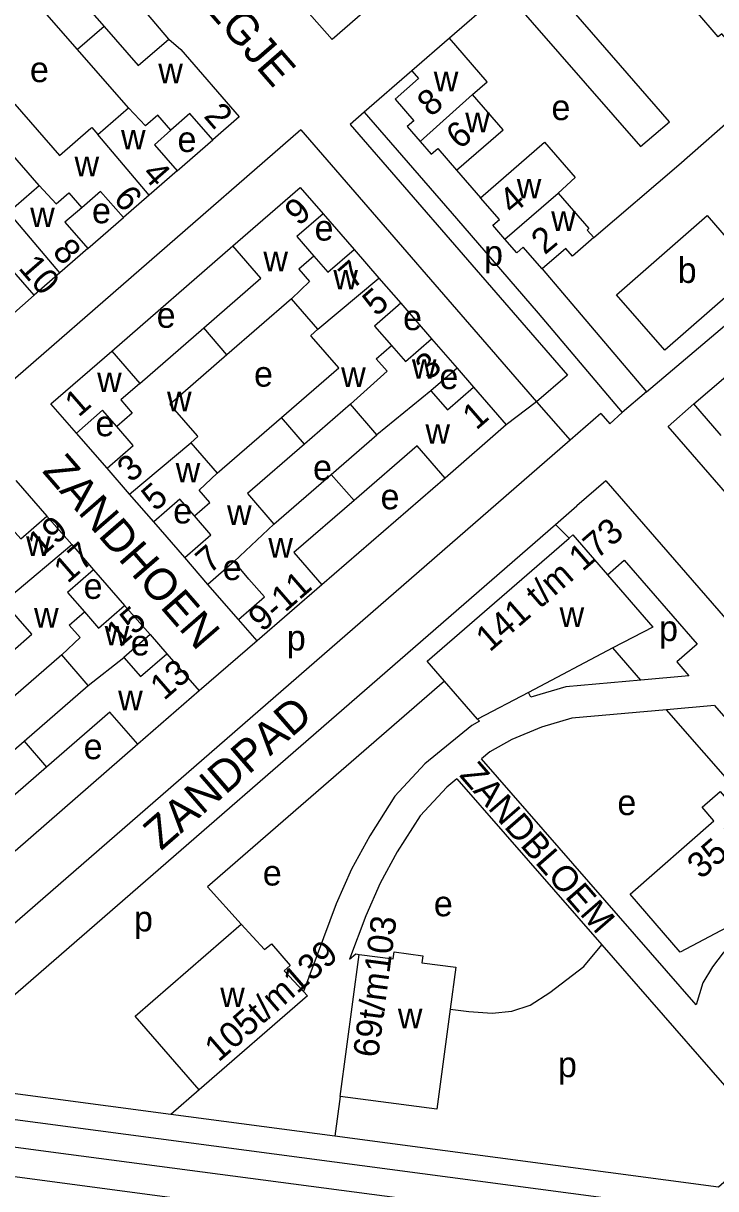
# Model space of a CAD drawing. Extents: x 155854 to 157362, y 383621 to 384685.
# Drawn here: x 156185.4 to 156294.2, y 383977 to 384160.1 of the extents above; entities that cross this region are included whole.
import ezdxf

# ---------------------------------------------------------------- set-up
doc = ezdxf.new("R2010")
doc.units = 0
for name, color, linetype in [('BLT_Basislijn', 7, 'Continuous'), ('BLT_Bebouwing', 7, 'Continuous'), ('BLT_Centroide', 7, 'Continuous'), ('BLT_Huisnummer', 7, 'Continuous'), ('BLT_Huisnummer_ tussenligend', 7, 'Continuous'), ('BLT_Huisnummer_reeks', 7, 'Continuous'), ('BLT_Onderverdeling_panden', 7, 'Continuous'), ('BLT_Straatnaam', 7, 'Continuous'), ('BLT_Straatnaam_verkleind', 7, 'Continuous')]:
    doc.layers.add(name, color=color, linetype=linetype)

msp = doc.modelspace()

# ---------------------------------------------------------------- linework, layer by layer
at = {"layer": 'BLT_Basislijn'}
for p, q in [((156208.25, 384157.66), (156195.11, 384173.27)), ((156261.02, 384165.3), (156252.38, 384157.81)), ((156246.43, 384152.66), (156238.97, 384146.18)), ((156288.38, 384137.89), (156302.08, 384149.93)), ((156238.97, 384146.18), (156236.73, 384144.23)), ((156238.97, 384146.18), (156253.47, 384129.45)), ((156228.99, 384143.37), (156119.21, 384047.9)), ((156209.57, 384136.94), (156215.16, 384141.83)), ((156253.48, 384137.07), (156257.24, 384132.72)), ((156275.02, 384126.47), (156288.38, 384137.89)), ((156195.52, 384124.75), (156201.13, 384129.6)), ((156232.5, 384130.2), (156237.37, 384124.59)), ((156199.29, 384108.63), (156218.31, 384125.15)), ((156283.29, 384102.22), (156307.03, 384122.29)), ((156181.54, 384112.55), (156187.1, 384117.41)), ((156244.7, 384116.14), (156249.55, 384110.55)), ((156253.55, 384105.95), (156256.15, 384102.97)), ((156270.89, 384104.85), (156266.05, 384100.66)), ((156283.29, 384102.22), (156279.5, 384098.96)), ((156266.05, 384100.66), (156261.29, 384097.05)), ((156266.05, 384100.66), (156271.3, 384094.61)), ((156286.74, 384096.77), (156290.76, 384100.33)), ((156276.14, 384098.81), (156271.3, 384094.61)), ((156276.14, 384098.81), (156277.53, 384097.2)), ((156279.5, 384098.96), (156277.53, 384097.2)), ((156198.56, 384090.23), (156193.75, 384095.75)), ((156184.24, 384088.28), (156189.1, 384082.69)), ((156251.66, 384088.68), (156232.31, 384071.9)), ((156276.92, 384088.24), (156272.39, 384084.3)), ((156210.77, 384076.18), (156205.89, 384081.79)), ((156269.03, 384081.38), (156271.15, 384079.26)), ((156196.45, 384074.27), (156201.32, 384068.67)), ((156219.2, 384066.47), (156214.4, 384071.98)), ((156205.31, 384064.1), (156207.93, 384061.07)), ((156222.13, 384063.09), (156213.04, 384055.23)), ((156282.43, 384056.94), (156278.04, 384061.99)), ((156289.95, 384057.62), (156282.43, 384056.94)), ((156293.99, 384052.96), (156286.48, 384052.28)), ((156293.99, 384052.96), (156302.93, 384042.66)), ((156298.33, 384038.66), (156286.48, 384052.28)), ((156203.42, 384046.86), (156184.1, 384030.05)), ((156291.12, 384005.94), (156257.4, 384044.59)), ((156253.52, 384041.43), (156276.3, 384015.32)), ((156213.04, 383992.55), (156208.6, 383988.69)), ((156235.2, 383991.54), (156234.37, 383985.27)), ((156189.73, 383982.81), (156254.44, 383974.29))]:
    msp.add_line(p, q, dxfattribs=at)
for points in [[(156274.95, 384193.23), (156233.91, 384157.58), (156227.55, 384164.87)], [(156284.47, 384142.57), (156286.91, 384144.67), (156265.55, 384169.24)], [(156261.02, 384165.3), (156282.35, 384140.75), (156284.47, 384142.57)], [(156236.73, 384144.23), (156270.89, 384104.85)], [(156228.99, 384143.37), (156266.05, 384100.66)], [(156253.47, 384129.45), (156266.29, 384114.57), (156279.5, 384098.96)], [(156266.94, 384121.54), (156270.1, 384117.8), (156283.29, 384102.22)], [(156324.05, 384062.01), (156320.05, 384058.42), (156286.74, 384096.77)], [(156271.3, 384094.61), (156165.88, 384003.01), (156161.13, 383998.95)], [(156276.92, 384088.24), (156307.18, 384053.41), (156310.96, 384056.69), (156314.93, 384052.11), (156311.16, 384048.83), (156362.68, 383989.52), (156366.72, 383992.5), (156368.14, 383991.05), (156369.04, 383989.47), (156370.17, 383986.09), (156370.85, 383982.49), (156370.38, 383978.82), (156369.95, 383975.5), (156367.77, 383974.52)], [(156269.03, 384081.38), (156272.39, 384084.3)], [(156169.94, 383993.83), (156170.15, 383995.49), (156269.03, 384081.38)], [(156277.17, 384073.47), (156279.79, 384075.78), (156291.26, 384062.56), (156288.06, 384059.8), (156289.95, 384057.62)], [(156251.58, 384056.78), (156214.36, 384024.48), (156219.64, 384018.6)], [(156282.43, 384056.94), (156270.65, 384055.87), (156265.14, 384054.28), (156264.76, 384055.01)], [(156256.77, 384050.81), (156257.07, 384050.47), (156255.88, 384049.79), (156248.5, 384043.8), (156243.75, 384038.7), (156239.82, 384032.47), (156236.98, 384027.22), (156234.57, 384021.78), (156229.44, 384007.99)], [(156286.48, 384052.28), (156271.57, 384050.94), (156266.81, 384049.56), (156262.15, 384047.6), (156258.71, 384045.65), (156257.4, 384044.59)], [(156253.52, 384041.43), (156251.92, 384040.13), (156247.73, 384035.63), (156244.14, 384029.94), (156241.47, 384025.02), (156239.2, 384019.89), (156236.67, 384013.07)], [(156313.3, 384021.14), (156305.72, 384020.42), (156301.83, 384018.84), (156297.89, 384016.37), (156295.36, 384014.11), (156293.66, 384011.87), (156292.16, 384009.4), (156291.12, 384005.94)], [(156236.67, 384013.07), (156237.63, 384013.91), (156238.16, 384013.85)], [(156252.47, 384005.26), (156255.42, 384004.86), (156259.08, 384004.63), (156262.15, 384004.93), (156265.04, 384005.87), (156268.11, 384007.86), (156273.48, 384011.95), (156276.3, 384015.32)], [(156276.3, 384015.32), (156303.06, 383984.64), (156294.62, 383977.28)], [(156208.6, 383988.69), (156169.94, 383993.83)], [(156169.45, 383989.86), (156266.3, 383977), (156363.4, 383964.11)], [(156234.37, 383985.27), (156208.6, 383988.69)], [(156168.92, 383985.6), (156189.73, 383982.81)], [(156294.62, 383977.28), (156234.37, 383985.27)], [(156167.95, 383981.03), (156181.65, 383979.24), (156217.42, 383974.51), (156229.18, 383972.97)]]:
    msp.add_lwpolyline(points, dxfattribs=at)
at = {"layer": 'BLT_Bebouwing'}
for p, q in [((156252.38, 384157.81), (156246.43, 384152.66)), ((156247.48, 384151.44), (156243.8, 384148.23)), ((156246.43, 384152.66), (156247.48, 384151.44)), ((156243.8, 384148.23), (156246.76, 384144.83)), ((156260.77, 384143.38), (156255.98, 384148.94)), ((156246.76, 384144.83), (156245.72, 384143.91)), ((156245.72, 384143.91), (156247.74, 384141.58)), ((156253.48, 384137.07), (156260.77, 384143.38)), ((156247.74, 384141.58), (156249.47, 384139.58)), ((156249.47, 384139.58), (156250.51, 384140.47)), ((156250.51, 384140.47), (156253.48, 384137.07)), ((156257.24, 384132.72), (156267.29, 384141.45)), ((156209.57, 384136.94), (156205.16, 384133.11)), ((156205.16, 384133.11), (156201.13, 384129.6)), ((156195.52, 384124.75), (156191.13, 384120.92)), ((156237.37, 384124.59), (156241.26, 384120.11)), ((156191.13, 384120.92), (156187.1, 384117.41)), ((156241.26, 384120.11), (156244.7, 384116.14)), ((156249.55, 384110.55), (156253.55, 384105.95)), ((156290.76, 384100.33), (156299.59, 384107.93)), ((156236.79, 384100.27), (156229.59, 384094.02)), ((156240.96, 384095.48), (156236.79, 384100.27)), ((156295.06, 384095.39), (156290.76, 384100.33)), ((156233.79, 384089.26), (156240.96, 384095.48)), ((156202.11, 384086.14), (156198.56, 384090.23)), ((156205.89, 384081.79), (156202.11, 384086.14)), ((156189.1, 384082.69), (156193, 384078.22)), ((156214.4, 384071.98), (156210.77, 384076.18)), ((156278.04, 384061.99), (156264.76, 384055.01)), ((156256.77, 384050.81), (156251.58, 384056.78)), ((156264.76, 384055.01), (156256.77, 384050.81)), ((156229.44, 384007.99), (156230.06, 384007.33))]:
    msp.add_line(p, q, dxfattribs=at)
for points in [[(156190.05, 384168.86), (156198.09, 384159.64)], [(156296.46, 384156.93), (156295.13, 384158.46), (156294.6, 384158), (156291.06, 384162.08), (156298.34, 384168.39)], [(156193.94, 384156.01), (156186.91, 384164.09), (156181.97, 384159.8)], [(156198.09, 384159.64), (156203.45, 384153.48), (156208.25, 384157.66)], [(156208.25, 384157.66), (156210.14, 384156), (156219.29, 384145.43), (156215.16, 384141.83)], [(156255.98, 384148.94), (156258.29, 384150.92), (156252.38, 384157.81)], [(156201.91, 384146.84), (156193.94, 384156.01)], [(156184.07, 384147.43), (156191.1, 384139.35), (156196.03, 384143.64)], [(156197.11, 384142.67), (156201.91, 384146.84)], [(156215.16, 384141.83), (156211.58, 384145.94), (156208.6, 384143.33)], [(156187.88, 384134.62), (156179.9, 384143.79)], [(156196.03, 384143.64), (156196.17, 384143.75), (156197.11, 384142.67)], [(156208.6, 384143.33), (156205.99, 384141.05), (156209.57, 384136.94)], [(156267.29, 384141.45), (156272.11, 384135.9), (156269.46, 384133.44)], [(156183.08, 384130.45), (156187.88, 384134.62)], [(156201.13, 384129.6), (156197.55, 384133.71), (156194.58, 384131.14)], [(156218.31, 384125.15), (156228.9, 384134.34), (156232.5, 384130.2)], [(156269.46, 384133.44), (156274.23, 384127.88), (156273.97, 384127.65), (156275.02, 384126.47)], [(156194.58, 384131.14), (156191.94, 384128.86), (156195.52, 384124.75)], [(156261.08, 384126.21), (156259.18, 384128.39), (156260.21, 384129.32), (156257.24, 384132.72)], [(156232.5, 384130.2), (156228.39, 384126.62), (156231.05, 384123.56)], [(156286.19, 384108.79), (156278.6, 384117.47), (156292.87, 384129.91), (156298.15, 384123.82), (156301.96, 384125.68), (156303.55, 384123.89), (156286.19, 384108.79)], [(156266.94, 384121.54), (156263.96, 384124.96), (156262.94, 384124.08), (156261.08, 384126.21)], [(156275.02, 384126.47), (156271.68, 384123.55)], [(156213.74, 384112.28), (156222.71, 384120.08), (156218.31, 384125.15)], [(156231.05, 384123.56), (156233.25, 384121.02), (156237.37, 384124.59)], [(156271.68, 384123.55), (156270.63, 384124.73), (156266.94, 384121.54)], [(156187.1, 384117.41), (156183.52, 384121.52), (156180.55, 384118.92)], [(156227.53, 384116.84), (156217.4, 384108.05)], [(156231.69, 384112.05), (156227.53, 384116.84)], [(156244.7, 384116.14), (156240.59, 384112.57), (156243.25, 384109.5)], [(156203.69, 384103.56), (156213.74, 384112.28)], [(156225.97, 384098.2), (156234.96, 384106.02), (156230.69, 384110.94)], [(156230.69, 384110.94), (156230.57, 384111.08), (156231.69, 384112.05)], [(156243.25, 384109.5), (156245.44, 384106.97), (156249.55, 384110.55)], [(156193.75, 384095.75), (156189.74, 384100.34), (156199.29, 384108.63)], [(156199.29, 384108.63), (156203.69, 384103.56)], [(156217.4, 384108.05), (156208.42, 384100.26), (156212.7, 384095.33)], [(156253.55, 384105.95), (156249.44, 384102.38)], [(156249.44, 384102.38), (156252.04, 384099.39)], [(156252.04, 384099.39), (156256.15, 384102.97)], [(156256.15, 384102.97), (156261.29, 384097.05)], [(156200.09, 384096.76), (156197.86, 384099.34), (156193.75, 384095.75)], [(156215.88, 384089.43), (156225.97, 384098.2)], [(156198.56, 384090.23), (156202.67, 384093.8), (156200.09, 384096.76)], [(156261.29, 384097.05), (156251.66, 384088.68)], [(156212.7, 384095.33), (156212.81, 384095.19), (156211.71, 384094.23)], [(156211.71, 384094.23), (156215.88, 384089.43)], [(156229.59, 384094.02), (156220.6, 384086.23), (156224.76, 384081.43)], [(156251.66, 384088.68), (156247.27, 384093.74), (156237.36, 384085.14)], [(156224.76, 384081.43), (156233.79, 384089.26)], [(156212.3, 384082.72), (156210.01, 384085.36), (156205.89, 384081.79)], [(156237.36, 384085.14), (156227.92, 384076.96), (156232.31, 384071.9)], [(156182.78, 384081.65), (156184.99, 384079.11), (156189.1, 384082.69)], [(156210.77, 384076.18), (156214.89, 384079.74), (156212.3, 384082.72)], [(156193, 384078.22), (156196.45, 384074.27)], [(156248.85, 384059.93), (156271.15, 384079.26)], [(156271.15, 384079.26), (156271.72, 384079.74), (156277.17, 384073.47)], [(156218.52, 384075.55), (156214.4, 384071.98)], [(156220.86, 384072.8), (156218.52, 384075.55)], [(156196.45, 384074.27), (156192.34, 384070.69), (156194.99, 384067.64)], [(156219.2, 384066.47), (156223.32, 384070.04), (156220.86, 384072.8)], [(156277.17, 384073.47), (156284.29, 384065.28)], [(156232.31, 384071.9), (156222.13, 384063.09)], [(156177.74, 384056.31), (156186.75, 384064.13), (156182.46, 384069.07)], [(156194.99, 384067.64), (156197.22, 384065.08), (156201.32, 384068.67)], [(156201.32, 384068.67), (156205.31, 384064.1)], [(156222.13, 384063.09), (156219.2, 384066.47)], [(156284.29, 384065.28), (156278.04, 384061.99)], [(156205.31, 384064.1), (156201.21, 384060.51)], [(156191.44, 384060.91), (156181.36, 384052.14)], [(156195.61, 384056.11), (156191.44, 384060.91)], [(156201.21, 384060.51), (156203.83, 384057.49)], [(156203.83, 384057.49), (156207.93, 384061.07)], [(156207.93, 384061.07), (156213.04, 384055.23)], [(156251.58, 384056.78), (156248.85, 384059.93)], [(156185.53, 384047.36), (156195.61, 384056.11)], [(156213.04, 384055.23), (156203.42, 384046.86)], [(156203.42, 384046.86), (156199.02, 384051.92), (156189.07, 384043.28)], [(156176.52, 384039.53), (156185.53, 384047.36)], [(156189.07, 384043.28), (156179.68, 384035.12), (156184.1, 384030.05)], [(156280.73, 384023.33), (156293.89, 384034.82), (156292.04, 384036.95), (156294.89, 384039.42), (156296.74, 384037.3), (156298.33, 384038.66)], [(156309.63, 384025.29), (156288.58, 384014.2), (156280.73, 384023.33)], [(156213.04, 383992.55), (156202.98, 384004.13), (156219.64, 384018.6)], [(156219.64, 384018.6), (156223.3, 384014.6), (156224.37, 384015.52), (156227.33, 384012.11), (156226.37, 384011.28), (156229.44, 384007.99)], [(156238.16, 384013.85), (156243.53, 384013.13), (156243.68, 384014.25), (156248.16, 384013.64), (156248.01, 384012.54), (156253.34, 384011.82)], [(156235.2, 383991.54), (156238.16, 384013.85)], [(156253.34, 384011.82), (156252.47, 384005.26)], [(156230.06, 384007.33), (156213.04, 383992.55)], [(156252.47, 384005.26), (156250.39, 383989.53), (156235.2, 383991.54)]]:
    msp.add_lwpolyline(points, dxfattribs=at)
at = {"layer": 'BLT_Onderverdeling_panden'}
for p, q in [((156247.74, 384141.58), (156255.98, 384148.94)), ((156205.16, 384133.11), (156197.11, 384142.67)), ((156261.08, 384126.21), (156269.46, 384133.44)), ((156191.13, 384120.92), (156183.08, 384130.45)), ((156231.69, 384112.05), (156241.26, 384120.11)), ((156217.4, 384108.05), (156213.74, 384112.28)), ((156249.44, 384102.38), (156240.96, 384095.48)), ((156202.11, 384086.14), (156211.71, 384094.23)), ((156224.76, 384081.43), (156218.52, 384075.55)), ((156183.45, 384070.17), (156193, 384078.22)), ((156195.61, 384056.11), (156201.21, 384060.51)), ((156185.53, 384047.36), (156189.07, 384043.28))]:
    msp.add_line(p, q, dxfattribs=at)
for points in [[(156198.09, 384159.64), (156193.94, 384156.01)], [(156208.6, 384143.33), (156206.54, 384145.69), (156204.6, 384144), (156201.91, 384146.84)], [(156187.88, 384134.62), (156190.56, 384131.79), (156192.53, 384133.5), (156194.58, 384131.14)], [(156231.05, 384123.56), (156228.67, 384121.49), (156230.36, 384119.54), (156227.53, 384116.84)], [(156236.79, 384100.27), (156242.56, 384105.47), (156240.86, 384107.43), (156243.25, 384109.5)], [(156203.69, 384103.56), (156200.71, 384100.96), (156202.52, 384098.88), (156200.09, 384096.76)], [(156229.59, 384094.02), (156225.97, 384098.2)], [(156212.3, 384082.72), (156214.72, 384084.82), (156213.04, 384086.76), (156215.88, 384089.43)], [(156237.36, 384085.14), (156233.79, 384089.26)], [(156191.44, 384060.91), (156194.31, 384063.62), (156192.62, 384065.57), (156194.99, 384067.64)]]:
    msp.add_lwpolyline(points, dxfattribs=at)

# ---------------------------------------------------------------- texts
at = {"layer": 'BLT_Centroide'}
for s, p in [('e', (156186.44, 384150.88)), ('w', (156206.61, 384150.72)), ('w', (156249.89, 384149.45)), ('e', (156268.38, 384144.92)), ('w', (156254.84, 384143)), ('w', (156200.75, 384140.31)), ('e', (156209.63, 384139.91)), ('w', (156193.45, 384136.09)), ('w', (156262.93, 384132.62)), ('w', (156186.48, 384128.11)), ('e', (156196.19, 384128.71)), ('w', (156268.34, 384127.5)), ('e', (156231.16, 384125.99)), ('w', (156223.12, 384121.17)), ('p', (156257.79, 384122.03)), ('b', (156288.21, 384119.34)), ('w', (156234.11, 384118.31)), ('e', (156206.35, 384112.29)), ('e', (156245.07, 384111.92)), ('w', (156246.45, 384104.28)), ('e', (156221.65, 384103.04)), ('w', (156235.34, 384102.98)), ('e', (156250.78, 384102.66)), ('w', (156197, 384102.19)), ('w', (156207.98, 384099.19)), ('e', (156196.73, 384095.25)), ('w', (156248.58, 384094.06)), ('w', (156209.34, 384088)), ('e', (156230.92, 384088.34)), ('e', (156241.53, 384083.77)), ('e', (156208.95, 384081.55)), ('w', (156217.41, 384081.32)), ('w', (156185.84, 384076.44)), ('w', (156223.9, 384076.19)), ('e', (156216.72, 384072.66)), ('e', (156194.88, 384069.7)), ('w', (156187.09, 384065.19)), ('w', (156269.66, 384065.28)), ('w', (156198.18, 384062.38)), ('p', (156285.29, 384063.08)), ('e', (156202.28, 384060.81)), ('p', (156226.8, 384061.59)), ('w', (156200.3, 384052.19)), ('e', (156194.88, 384044.51)), ('e', (156278.74, 384035.73)), ('e', (156223.03, 384024.66)), ('e', (156249.9, 384019.83)), ('p', (156202.79, 384017.46)), ('w', (156216.34, 384005.56)), ('w', (156244.25, 384002.25)), ('p', (156269.4, 383994.56))]:
    msp.add_text(s, height=4, dxfattribs=at).set_placement(p)
at = {"layer": 'BLT_Huisnummer'}
for s, rotation, p in [('8', 39.9106, (156249.41, 384145.29)), ('2', 310.9798, (156213.62, 384145.48)), ('6', 39.9106, (156253.95, 384140.18)), ('6', 310.9798, (156199.4, 384132.5)), ('4', 39.9106, (156262.26, 384129.95)), ('9', 40.9742, (156228.66, 384128.15)), ('2', 39.9106, (156267.32, 384123.65)), ('5', 40.9742, (156240.87, 384113.94)), ('1', 40.9807, (156194.09, 384098.13)), ('1', 40.9742, (156256.57, 384096.11)), ('5', 40.9807, (156206.15, 384083.33)), ('17', 40.9807, (156192.36, 384072.02)), ('13', 40.9807, (156207.51, 384053.63))]:
    msp.add_text(s, height=4, rotation=rotation, dxfattribs=at).set_placement(p)
at = {"layer": 'BLT_Huisnummer_ tussenligend'}
for s, rotation, p in [('4', 310.9798, (156203.88, 384136.37)), ('8', 310.9798, (156189.82, 384124.14)), ('10', 310.9798, (156184.5, 384121.62)), ('7', 40.9742, (156237.14, 384118.23)), ('3', 40.9742, (156249.17, 384103.92)), ('3', 40.9807, (156202.32, 384087.84)), ('19', 40.9807, (156188.25, 384076.16)), ('7', 40.9807, (156214.66, 384073.51)), ('15', 40.9807, (156200.53, 384061.95))]:
    msp.add_text(s, height=4, rotation=rotation, dxfattribs=at).set_placement(p)
at = {"layer": 'BLT_Huisnummer_reeks'}
for s, rotation, p in [('141 t/m 173', 40.919, (156258.67, 384061.24)), ('9-11', 40.9825, (156222.93, 384064.37)), ('35 t/m 67', 40.9822, (156291.88, 384025.53)), ('69t/m103', 82.4421, (156241.15, 383997.51)), ('105t/m139', 40.9812, (156216.07, 383996.82))]:
    msp.add_text(s, height=4, rotation=rotation, dxfattribs=at).set_placement(p)
at = {"layer": 'BLT_Straatnaam'}
for s, rotation, p in [('ZANDVLIEGJE', 310.9818, (156194.8, 384184.31)), ('ZANDHOEN', 310.9821, (156188.26, 384089.7)), ('ZANDPAD', 40.982, (156207.05, 384030.06))]:
    msp.add_text(s, height=5, rotation=rotation, dxfattribs=at).set_placement(p)
at = {"layer": 'BLT_Straatnaam_verkleind'}
msp.add_text('ZANDBLOEM', height=4, rotation=311.0275, dxfattribs=at).set_placement((156253.79, 384041.93))

doc.saveas('drawing.dxf')
